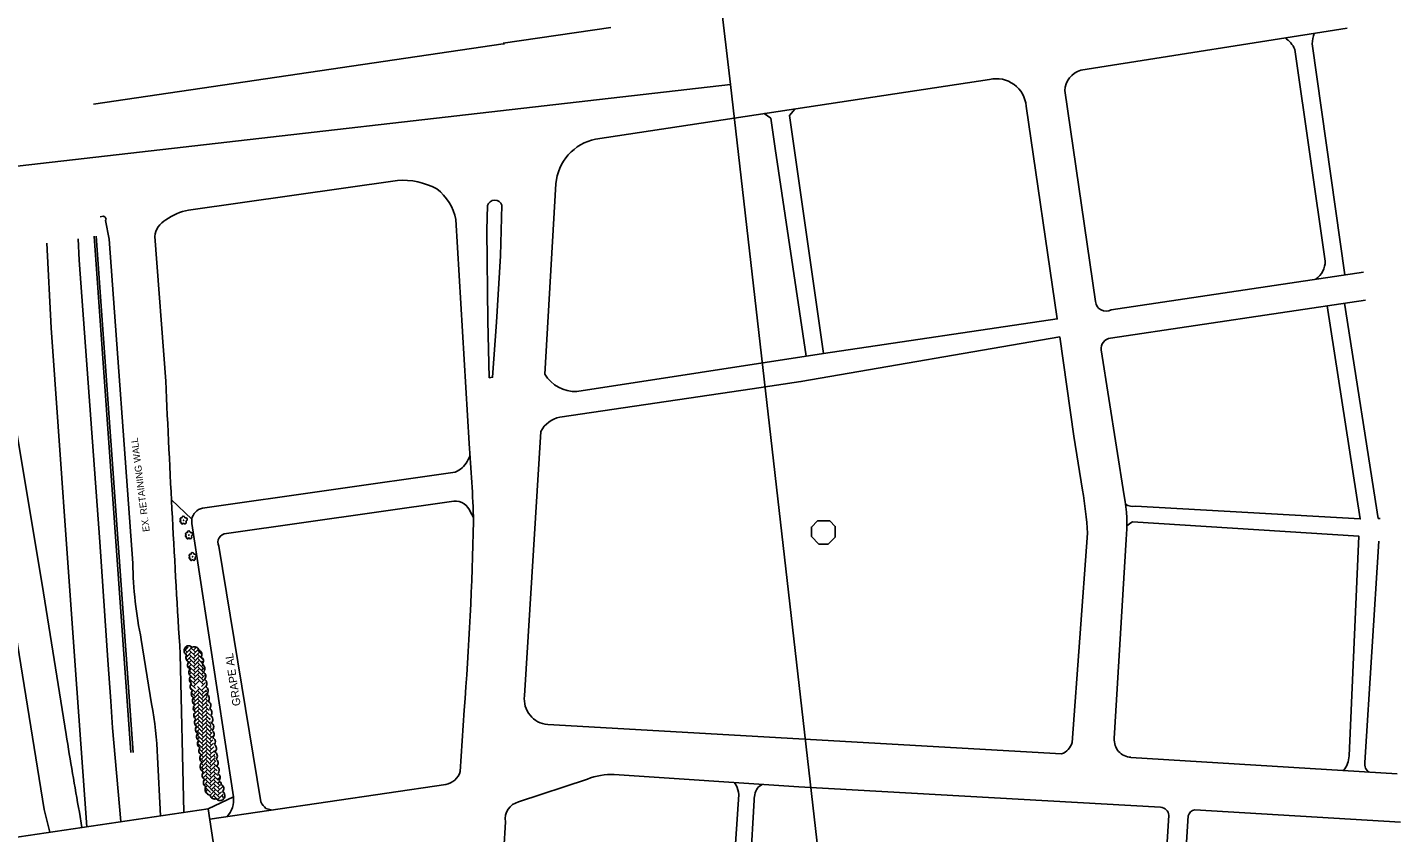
# Model space of a CAD drawing. Extents: x -9648 to 41057, y -12373 to 40276.
# Drawn here: x 9212 to 10174, y -1624 to -1060 of the extents above; entities that cross this region are included whole.
import ezdxf

# ---------------------------------------------------------------- set-up
doc = ezdxf.new("R2010")
doc.units = 0
doc.layers.add('SC_Scratch1', color=7, linetype='Continuous')
doc.layers.add('SH_Data', color=7, linetype='Continuous')

msp = doc.modelspace()

# ---------------------------------------------------------------- linework, layer by layer
at = {"layer": 'SC_Scratch1'}
for p, q in [((9447.3, 1145.16), (9704.49, -1100.16)), ((9447.3, 1145.16), (9704.49, -1100.16)), ((8174.5, -1275.41), (9704.49, -1100.16)), ((9704.49, -1100.16), (8174.5, -1275.41)), ((9704.49, -1100.16), (8174.5, -1275.41)), ((9704.49, -1100.16), (9961.68, -3345.48))]:
    msp.add_line(p, q, dxfattribs=at)
at = {"layer": 'SH_Data'}
for p, q in [((9545.55, -1071.29), (9620.74, -1060.25)), ((9949.76, -1090.26), (10136.31, -1060.72)), ((9258.78, -1113.84), (9545.55, -1071.81)), ((9545.55, -1071.81), (9546.35, -1071.69)), ((10099.55, -1075.57), (10120.83, -1223.76)), ((10111.75, -1071.77), (10134.51, -1233.49)), ((9610.18, -1138.45), (9885.96, -1096.7)), ((9960.05, -1252.05), (9938.57, -1104.47)), ((9325.21, -1188.21), (9471.4, -1167.33)), ((9574.68, -1302.87), (9582.4, -1169.67)), ((9263.42, -1192.85), (9265.42, -1192.44)), ((9512.42, -1194.71), (9521.7, -1351.5)), ((9259.16, -1206.36), (9284.93, -1567.94)), ((9260.66, -1206.26), (9286.42, -1567.83)), ((9309.28, -1307.77), (9301.62, -1206.62)), ((10147.75, -1231.51), (9971.05, -1257.85)), ((9970.66, -1277.85), (10149.07, -1251.11)), ((9980.12, -1388.24), (9964.07, -1286.05)), ((9560.4, -1528.28), (9571.9, -1343.07)), ((9520.31, -1364.1), (9522.11, -1360.5)), ((9334.93, -1396.81), (9511.91, -1371.51)), ((9313.28, -1390.92), (9327.53, -1404.59)), ((9510.93, -1391.9), (9351.74, -1414.59)), ((9524.73, -1403.3), (9522.53, -1399.7)), ((9238.65, -1405.75), (9247.03, -1522.96)), ((9356.64, -1598.79), (9327.53, -1407.41)), ((9954.54, -1414.26), (9943.82, -1560.86)), ((9973.22, -1558.05), (9981.54, -1418.84)), ((10158.34, -1419.94), (10148.63, -1574.75)), ((9346.54, -1423.4), (9375.85, -1602.38)), ((9292.18, -1488.83), (9299.4, -1533.82)), ((9322.05, -1609.61), (9319.39, -1498.98)), ((9324.35, -1497.67), (9322.85, -1496.18)), ((9322.93, -1496.26), (9325.07, -1494.11)), ((9323.21, -1498.81), (9327.18, -1494.84)), ((9324.35, -1494.84), (9323.47, -1493.97)), ((9323.55, -1501.3), (9327.18, -1497.67)), ((9330.01, -1500.5), (9325.76, -1496.26)), ((9330.01, -1503.33), (9325.76, -1499.09)), ((9330.01, -1497.67), (9326.59, -1494.25)), ((9328.59, -1496.26), (9330.25, -1494.59)), ((9328.59, -1499.08), (9332.2, -1495.47)), ((9328.59, -1501.91), (9332.83, -1497.67)), ((9330, -1494.84), (9329.7, -1494.54)), ((9334.47, -1499.3), (9331.42, -1496.26)), ((9334.9, -1502.56), (9331.42, -1499.08)), ((9334.25, -1499.08), (9334.42, -1498.91)), ((9270.73, -1531.81), (9268.78, -1503.17)), ((9324.35, -1503.33), (9323.74, -1502.72)), ((9324.35, -1500.5), (9323.79, -1499.94)), ((9324.13, -1503.55), (9327.18, -1500.5)), ((9324.65, -1505.86), (9327.18, -1503.33)), ((9325.07, -1508.27), (9327.18, -1506.16)), ((9330.01, -1506.16), (9325.76, -1501.91)), ((9330.01, -1508.98), (9325.76, -1504.74)), ((9330.01, -1511.81), (9325.77, -1507.57)), ((9328.59, -1504.74), (9332.83, -1500.49)), ((9328.6, -1507.57), (9332.84, -1503.32)), ((9328.6, -1510.4), (9332.84, -1506.15)), ((9330.81, -1499.66), (9330.81, -1499.66)), ((9335.1, -1505.58), (9331.42, -1501.91)), ((9335.67, -1508.98), (9331.42, -1504.74)), ((9335.54, -1511.68), (9331.43, -1507.57)), ((9334.25, -1501.91), (9334.67, -1501.49)), ((9334.25, -1504.74), (9335.07, -1503.91)), ((9334.25, -1507.56), (9335.41, -1506.41)), ((9325.6, -1510.57), (9327.18, -1508.98)), ((9330.01, -1514.64), (9325.77, -1510.4)), ((9325.77, -1513.23), (9327.18, -1511.81)), ((9326.94, -1514.4), (9325.77, -1513.23)), ((9330.02, -1520.29), (9325.91, -1516.19)), ((9326, -1515.82), (9327.19, -1514.64)), ((9326.3, -1518.36), (9327.19, -1517.47)), ((9330.01, -1517.47), (9326.96, -1514.42)), ((9328.6, -1513.23), (9332.84, -1508.98)), ((9328.6, -1516.06), (9332.84, -1511.81)), ((9328.6, -1518.88), (9332.84, -1514.64)), ((9328.61, -1521.71), (9332.84, -1517.47)), ((9335.67, -1514.64), (9331.43, -1510.39)), ((9335.67, -1517.46), (9331.43, -1513.22)), ((9335.67, -1520.29), (9331.43, -1516.05)), ((9334.26, -1510.39), (9335.74, -1508.91)), ((9334.26, -1513.22), (9335.68, -1511.8)), ((9334.26, -1516.05), (9336.4, -1513.91)), ((9334.26, -1518.88), (9336.42, -1516.72)), ((9335.67, -1511.81), (9335.65, -1511.78)), ((9254.05, -1619.85), (9247.03, -1522.96)), ((9330.02, -1525.95), (9326.41, -1522.35)), ((9326.42, -1521.07), (9327.19, -1520.3)), ((9326.86, -1523.46), (9327.19, -1523.13)), ((9330.02, -1523.12), (9326.88, -1519.98)), ((9330.02, -1528.78), (9327.24, -1526.01)), ((9328.61, -1527.37), (9332.85, -1523.12)), ((9328.61, -1530.2), (9332.85, -1525.95)), ((9335.68, -1525.95), (9331.43, -1521.71)), ((9335.68, -1528.78), (9331.43, -1524.54)), ((9335.68, -1531.61), (9331.44, -1527.37)), ((9334.26, -1521.71), (9337.05, -1518.91)), ((9334.26, -1524.54), (9337.38, -1521.41)), ((9334.26, -1527.36), (9337.71, -1523.91)), ((9334.26, -1530.19), (9338.04, -1526.41)), ((9337.47, -1522.09), (9337.09, -1521.71)), ((9337.9, -1525.34), (9337.09, -1524.54)), ((9338.33, -1528.6), (9337.09, -1527.36)), ((9330.03, -1534.44), (9328.01, -1532.42)), ((9330.02, -1531.61), (9328.47, -1530.06)), ((9328.61, -1533.02), (9332.85, -1528.78)), ((9330.03, -1537.27), (9328.7, -1535.94)), ((9328.8, -1535.66), (9332.85, -1531.61)), ((9328.97, -1538.33), (9332.86, -1534.44)), ((9329.13, -1541), (9332.86, -1537.26)), ((9335.68, -1534.44), (9331.44, -1530.19)), ((9335.68, -1537.26), (9331.44, -1533.02)), ((9335.69, -1540.09), (9331.44, -1535.85)), ((9334.27, -1533.02), (9338.37, -1528.91)), ((9334.27, -1535.85), (9338.51, -1531.61)), ((9334.27, -1538.68), (9338.51, -1534.43)), ((9334.27, -1541.51), (9338.51, -1537.26)), ((9338.76, -1531.85), (9337.09, -1530.19)), ((9339.19, -1535.11), (9337.09, -1533.02)), ((9339.62, -1538.37), (9337.1, -1535.85)), ((9330.03, -1542.92), (9329.08, -1541.97)), ((9329.43, -1543.53), (9332.86, -1540.09)), ((9329.64, -1546.14), (9332.86, -1542.92)), ((9330.03, -1545.75), (9329.71, -1545.43)), ((9330.03, -1540.09), (9329.79, -1539.86)), ((9329.98, -1548.63), (9332.86, -1545.75)), ((9335.69, -1542.92), (9331.44, -1538.68)), ((9335.69, -1545.75), (9331.44, -1541.51)), ((9335.69, -1548.58), (9331.44, -1544.34)), ((9335.69, -1551.41), (9331.45, -1547.16)), ((9334.27, -1544.34), (9338.51, -1540.09)), ((9334.28, -1547.16), (9338.51, -1542.92)), ((9334.28, -1549.99), (9338.52, -1545.75)), ((9340.05, -1541.62), (9337.1, -1538.68)), ((9340.47, -1544.88), (9337.1, -1541.51)), ((9340.91, -1548.13), (9337.1, -1544.33)), ((9341.34, -1551.39), (9337.1, -1547.16)), ((9339.93, -1541.51), (9340.02, -1541.41)), ((9339.93, -1544.33), (9340.35, -1543.91)), ((9339.93, -1547.16), (9340.68, -1546.41)), ((9518.21, -1538.3), (9515.43, -1581.1)), ((9330.03, -1548.58), (9329.97, -1548.51)), ((9330.32, -1551.12), (9332.86, -1548.58)), ((9330.68, -1553.59), (9332.86, -1551.41)), ((9331, -1556.11), (9332.86, -1554.24)), ((9335.69, -1554.23), (9331.45, -1549.99)), ((9335.69, -1557.06), (9331.45, -1552.82)), ((9335.7, -1559.89), (9331.45, -1555.65)), ((9334.28, -1552.82), (9338.52, -1548.58)), ((9334.28, -1555.65), (9338.52, -1551.41)), ((9334.28, -1558.48), (9338.52, -1554.23)), ((9341.35, -1554.23), (9337.11, -1549.99)), ((9341.35, -1557.06), (9337.11, -1552.82)), ((9341.35, -1559.89), (9337.11, -1555.65)), ((9339.93, -1549.99), (9341.01, -1548.91)), ((9339.94, -1552.82), (9341.34, -1551.41)), ((9339.94, -1555.64), (9341.67, -1553.91)), ((9339.94, -1558.47), (9342, -1556.41)), ((9936.23, -1568.87), (9576.61, -1548.27)), ((9331.34, -1558.6), (9332.87, -1557.06)), ((9335.7, -1562.72), (9331.45, -1558.48)), ((9331.68, -1561.09), (9332.87, -1559.89)), ((9335.7, -1565.55), (9331.74, -1561.6)), ((9332.11, -1563.48), (9332.87, -1562.72)), ((9332.54, -1565.88), (9332.87, -1565.55)), ((9335.7, -1568.38), (9332.71, -1565.39)), ((9334.28, -1561.31), (9338.52, -1557.06)), ((9334.28, -1564.13), (9338.52, -1559.89)), ((9334.29, -1566.96), (9338.53, -1562.72)), ((9334.29, -1569.79), (9338.53, -1565.54)), ((9341.36, -1562.72), (9337.11, -1558.48)), ((9341.36, -1565.54), (9337.11, -1561.31)), ((9341.36, -1568.37), (9337.11, -1564.13)), ((9339.94, -1561.3), (9342.33, -1558.91)), ((9339.94, -1564.13), (9342.66, -1561.41)), ((9339.94, -1566.96), (9342.99, -1563.91)), ((9339.94, -1569.79), (9343.31, -1566.41)), ((9343.05, -1564.41), (9342.77, -1564.13)), ((9303.43, -1571.02), (9305.65, -1612.22)), ((9335.71, -1574.03), (9333.14, -1571.48)), ((9335.7, -1571.21), (9334.07, -1569.57)), ((9335.71, -1576.86), (9334.15, -1575.3)), ((9334.29, -1572.62), (9338.53, -1568.37)), ((9334.29, -1575.45), (9338.53, -1571.2)), ((9334.29, -1578.28), (9338.53, -1574.03)), ((9341.36, -1571.2), (9337.11, -1566.96)), ((9341.36, -1574.03), (9337.12, -1569.79)), ((9341.36, -1576.86), (9337.12, -1572.62)), ((9341.36, -1579.69), (9337.12, -1575.44)), ((9339.94, -1572.62), (9343.65, -1568.91)), ((9339.95, -1575.44), (9343.97, -1571.41)), ((9339.95, -1578.27), (9344.19, -1574.03)), ((9343.48, -1567.67), (9342.77, -1566.96)), ((9343.91, -1570.92), (9342.77, -1569.79)), ((9344.34, -1574.18), (9342.77, -1572.61)), ((9344.77, -1577.43), (9342.78, -1575.44)), ((10171.3, -1582.89), (9984.83, -1571.24)), ((9335.71, -1579.69), (9333.96, -1577.95)), ((9334.63, -1580.76), (9338.53, -1576.86)), ((9334.78, -1583.45), (9338.54, -1579.69)), ((9335.71, -1585.35), (9334.85, -1584.49)), ((9335.71, -1582.52), (9335.27, -1582.08)), ((9335.37, -1585.69), (9338.54, -1582.52)), ((9335.67, -1588.22), (9338.54, -1585.34)), ((9335.71, -1581.55), (9335.71, -1581.55)), ((9335.71, -1581.55), (9335.71, -1581.55)), ((9341.37, -1582.51), (9337.12, -1578.27)), ((9341.37, -1585.34), (9337.12, -1581.1)), ((9341.37, -1588.17), (9337.12, -1583.93)), ((9339.95, -1581.1), (9344.19, -1576.86)), ((9339.95, -1583.93), (9344.19, -1579.69)), ((9339.96, -1586.76), (9344.19, -1582.51)), ((9339.96, -1589.59), (9344.19, -1585.34)), ((9345.2, -1580.69), (9342.78, -1578.27)), ((9345.63, -1583.94), (9342.78, -1581.1)), ((9346.05, -1587.2), (9342.78, -1583.93)), ((9345.61, -1583.93), (9345.62, -1583.92)), ((9345.61, -1586.76), (9346.89, -1585.48)), ((9335.71, -1588.18), (9335.69, -1588.15)), ((9336.09, -1590.62), (9338.54, -1588.17)), ((9336.88, -1592.67), (9338.54, -1591)), ((9337.09, -1595.28), (9338.54, -1593.83)), ((9341.37, -1591), (9337.13, -1586.76)), ((9342.3, -1594.76), (9337.13, -1589.59)), ((9340.55, -1595.83), (9337.13, -1592.42)), ((9339.44, -1597.55), (9337.13, -1595.24)), ((9339.96, -1592.41), (9344.2, -1588.17)), ((9505.24, -1590.31), (9340.25, -1614.6)), ((9340.26, -1597.77), (9344.2, -1593.83)), ((9340.91, -1594.29), (9344.2, -1591)), ((9341.85, -1593.42), (9341.85, -1593.42)), ((9347.03, -1591), (9342.78, -1586.76)), ((9347.03, -1593.83), (9342.78, -1589.59)), ((9347.03, -1596.65), (9342.79, -1592.41)), ((9347.03, -1599.48), (9342.79, -1595.24)), ((9345.61, -1589.58), (9347.09, -1588.1)), ((9345.61, -1592.41), (9347.6, -1590.42)), ((9345.62, -1595.24), (9349.32, -1591.54)), ((9604.43, -1586.45), (9556.24, -1602.48)), ((9708.64, -1590.8), (9707.07, -1588.91)), ((9726.68, -1590.24), (9724.24, -1591.79)), ((9338.31, -1596.9), (9338.54, -1596.66)), ((9339.05, -1607.2), (9356.64, -1598.79)), ((9341.24, -1599.62), (9344.2, -1596.66)), ((9345.91, -1601.19), (9342.79, -1598.07)), ((9343.23, -1600.46), (9344.2, -1599.48)), ((9345.62, -1598.07), (9348.28, -1595.41)), ((9345.62, -1600.9), (9349.54, -1596.97)), ((9347.83, -1601.52), (9347.93, -1601.41)), ((9349.82, -1599.44), (9348.44, -1598.07)), ((9690, -1889.81), (9710.44, -1597.2)), ((9248.85, -1609.65), (9250.46, -1620.25)), ((9379.45, -1606.98), (9383.17, -1607.9)), ((9993.22, -1909.43), (10011.45, -1611.82)), ((10024.85, -1612.22), (10017.12, -1733.42)), ((10173.56, -1616.71), (10029.65, -1608.02)), ((9547.05, -1616.28), (9545.86, -1636.08))]:
    msp.add_line(p, q, dxfattribs=at)
for points in [[(9911.57, -1115.28), (9933.26, -1264.27), (9769.67, -1288.56), (9597.08, -1315.06)], [(9728.09, -1120.6), (9732.78, -1123.78), (9735.79, -1144.98), (9757.59, -1290.42)], [(9769.67, -1288.56), (9745.98, -1121.97), (9749.57, -1117.34)], [(9535.68, -1305.44), (9534.66, -1265.58), (9534.05, -1202.14), (9534.48, -1184.99)], [(9544.63, -1184.73), (9543.64, -1220.12), (9540.78, -1266.59), (9538.09, -1305.13), (9535.68, -1305.44)], [(9267.22, -1195.44), (9269.62, -1208.44), (9286.15, -1435.23)], [(9268.78, -1503.17), (9263.14, -1420.44), (9248.63, -1223.25), (9248.02, -1208.25)], [(9228.05, -1623.67), (9224.27, -1607.77), (9205.62, -1491.89), (9187.33, -1375.77), (9162.03, -1220.5)], [(9184.03, -1217.29), (9205.31, -1345.51), (9222.77, -1450.31), (9239.62, -1555.23)], [(9238.65, -1405.75), (9236.53, -1375.75), (9229.05, -1270.49), (9226.02, -1211.27)], [(9988.13, -1395.44), (10145.33, -1404.35), (10122.24, -1255.12)], [(10134.25, -1253.33), (10157.93, -1403.94), (10159.32, -1404.04)], [(9585.09, -1333.07), (9719.68, -1313.19), (9753.88, -1308.17), (9935.06, -1276.87)], [(9935.06, -1276.87), (9944.9, -1346.46), (9950.92, -1384.26)], [(9985.93, -1406.44), (10144.34, -1416.35), (10137.63, -1570.15)], [(9277.85, -1616.24), (9272.02, -1550.64), (9270.73, -1531.81)], [(9335.71, -1581.55), (9335.71, -1581.55)], [(10005.65, -1606.23), (9752.44, -1591.97), (9623.23, -1583.24)], [(9721.25, -1601.19), (9713.52, -1734.19), (10002.89, -1751.5)]]:
    msp.add_lwpolyline(points, dxfattribs=at)
for points in [[(9761.18, -1416.74), (9761.18, -1410.01), (9765.47, -1405.71), (9774.04, -1405.71), (9777.89, -1409.6), (9777.89, -1417), (9772.86, -1422.03), (9766.43, -1422.03)], [(9124.46, -1638.92), (9339.05, -1607.2), (9345.87, -1653.6), (9131.29, -1685.32)]]:
    msp.add_lwpolyline(points, close=True, dxfattribs=at)
for centre in [(9321.72, -1405.3), (9325.5, -1415.65), (9328.04, -1430.77)]:
    msp.add_circle(centre, 0.151, dxfattribs=at)
for centre, radius, start, end in [((10145.21, -1074.23), 33.56, 162.94118, 175.79118), ((10083.85, -1082.13), 17.01, 22.67918, 58.56618), ((9953.93, -1105.05), 15.37, 105.73518, 177.80118), ((9890.73, -1117.06), 20.91, 4.87218, 103.19018), ((9616.93, -1172.42), 34.63, 101.22518, 175.43618), ((9475.05, -1217.13), 49.93, 61.33918, 94.19618), ((9477.34, -1201.8), 35.79, 11.42818, 52.74318), ((9539.6, -1186.48), 5.33, 19.16818, 163.83318), ((9331.26, -1223.97), 36.27, 99.60118, 127.03518), ((9265.47, -1194.45), 2.01, 330.36518, 91.62618), ((9316.38, -1208.11), 14.83, 117.99218, 174.23718), ((10105.62, -1223.99), 15.21, 304.73918, 0.86918), ((9967.36, -1251.52), 7.33, 184.19218, 300.26918), ((9971.26, -1285.08), 7.26, 94.70818, 187.69618), ((9595.79, -1290.74), 24.35, 209.87718, 273.03818), ((20693.09, -801.91), 11395.04, 182.544183, 183.507183), ((9588.83, -1351.7), 19.01, 101.35418, 153.00418), ((8319.11, -1445.64), 1206.27, 1.87818, 4.47618), ((9505.26, -1355.49), 17.34, 292.57718, 330.24418), ((9512.03, -1402.8), 10.95, 16.44218, 95.78718), ((9671.13, -1433.21), 284.04, 3.82618, 9.92418), ((9874.9, -1408.45), 107.14, 354.43318, 10.87018), ((9321.61, -1403.44), 1.03, 351.9296, 194.2439), ((9336.8, -1405.99), 9.37, 101.50918, 171.43061), ((9986.48, -1385.23), 10.34, 238.14218, 279.15218), ((9319.94, -1405.92), 0.71, 86.78898, 298.7584), ((9320.15, -1404.39), 0.837, 56.61424, 257.82189), ((9320.81, -1407.13), 0.793, 131.84683, 12.32553), ((9322.63, -1406.8), 1.06, 188.95648, 53.358), ((9323.1, -1404.72), 1.23, 277.73186, 112.24144), ((9325.39, -1413.79), 1.03, 351.9296, 194.2439), ((9339.53, -1405.99), 12.08, 173.37778, 186.77007), ((7121.28, -1353.72), 2404.02, 355.59618, 358.75118), ((9995.43, -1424.27), 20.2, 118.03518, 131.72118), ((9323.71, -1416.27), 0.71, 86.78898, 298.7584), ((9323.93, -1414.74), 0.837, 56.61424, 257.82189), ((9324.58, -1417.48), 0.793, 131.84683, 12.32553), ((9326.41, -1417.15), 1.06, 188.95648, 53.358), ((9326.88, -1415.08), 1.23, 277.73186, 112.24144), ((9351.69, -1420.5), 5.9, 89.48118, 209.42518), ((9326.25, -1431.39), 0.71, 86.78898, 298.7584), ((9326.47, -1429.86), 0.837, 56.61424, 257.82189), ((9327.93, -1428.91), 1.03, 351.9296, 194.2439), ((9328.94, -1432.27), 1.06, 188.95648, 53.358), ((9329.41, -1430.19), 1.23, 277.73186, 112.24144), ((9587.66, -1428.45), 301.59, 181.28918, 191.54918), ((9327.12, -1432.6), 0.793, 131.84683, 12.32553), ((9325.19, -1496.55), 3.13, 139.75605, 249.75605), ((9325.39, -1496.16), 3.06, 37.78429, 147.78429), ((9329.47, -1496.87), 3.07, 12.75912, 122.75912), ((9331.51, -1499.1), 3.06, 321.81545, 71.81545), ((9326.5, -1501.51), 3.13, 139.75599, 249.75599), ((9327.66, -1506.58), 3.1, 136.39672, 246.39672), ((9332.6, -1503.78), 3.08, 314.69288, 64.69288), ((9333.13, -1509.1), 3.54, 312.29659, 62.29659), ((9328.44, -1511.72), 3.07, 131.25118, 241.25118), ((9328.92, -1516.77), 3.06, 129.51938, 239.51938), ((9334.19, -1514.5), 3.08, 314.69293, 64.69293), ((9335.04, -1519.48), 3.08, 314.69293, 64.69293), ((9329.51, -1521.74), 3.17, 132.8248, 242.8248), ((9330.24, -1526.74), 3.08, 134.69293, 244.69293), ((9335.66, -1524.65), 3.35, 312.5461, 62.5461), ((9336.69, -1529.95), 3.1, 316.39672, 66.39672), ((9082.63, -1576.07), 220.85, 1.31018, 11.02818), ((9331.01, -1531.78), 3.07, 132.97672, 242.97672), ((9331.64, -1536.83), 3.07, 131.25124, 241.25124), ((9337.69, -1534.93), 3.1, 316.39672, 66.39672), ((9338.54, -1539.8), 3.07, 312.97678, 62.97678), ((9578.11, -1530.49), 17.85, 172.89318, 265.18618), ((9332.04, -1541.93), 3.06, 127.78429, 237.78429), ((9332.43, -1546.83), 3.07, 131.25118, 241.25118), ((9339.16, -1544.74), 3.07, 311.25118, 61.25118), ((9339.6, -1549.89), 3.25, 311.05352, 61.05352), ((11156.04, -1258.19), 1939.31, 188.81018, 190.44118), ((9333.12, -1551.71), 3.08, 134.69293, 244.69293), ((9333.83, -1556.8), 3.07, 131.25118, 241.25118), ((9340.11, -1554.93), 3.06, 307.78429, 57.78429), ((9334.6, -1561.63), 3.1, 136.39672, 246.39672), ((9335.52, -1566.66), 3.08, 134.69293, 244.69293), ((9340.9, -1560.29), 3.13, 319.75605, 69.75605), ((9341.61, -1564.98), 3.15, 307.78429, 57.78429), ((9931.81, -1557.07), 12.59, 290.51218, 342.49018), ((9985.49, -1558.95), 12.3, 175.76518, 266.91618), ((9336.29, -1571.83), 3.16, 131.14945, 241.14945), ((9337.67, -1577.74), 4.28, 132.75216, 242.75216), ((9342.3, -1570.31), 3.1, 316.39672, 66.39672), ((9342.91, -1575.03), 3.06, 307.78429, 57.78429), ((10118.86, -1569.02), 18.8, 322.18018, 356.53918), ((10154.92, -1576.09), 6.43, 167.95318, 240.09118), ((9337.93, -1583.81), 3.18, 134.49162, 244.49162), ((9343.42, -1580.32), 3.18, 314.49156, 64.49156), ((9344.25, -1585.32), 3.07, 312.97678, 62.97678), ((9502.71, -1577.26), 13.29, 280.97118, 343.19118), ((9621.3, -1628.55), 45.35, 87.55418, 111.82918), ((9338.66, -1588.93), 3.07, 132.97672, 242.97672), ((9340.93, -1593.65), 4.17, 151.54919, 261.54919), ((9339.36, -1593.91), 3.07, 132.97678275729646, 132.97678441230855), ((9344.8, -1590.55), 3.35, 5.12803, 62.5461), ((9346.77, -1593.06), 3.13, 314.21479, 64.21479), ((9347.6, -1598.12), 3.13, 314.21484, 64.21484), ((9691.27, -1599.14), 19.27, 5.80718, 25.67418), ((9734.6, -1600.26), 13.39, 140.71018, 183.95318), ((9343.37, -1597.4), 3.07, 187.21792, 297.21792), ((9347.36, -1598.49), 3.06, 212.24308, 322.24308), ((9339.28, -1600.9), 17.49, 316.85821, 6.936), ((9387.29, -1597.13), 12.59, 204.66918, 231.48918), ((9559.01, -1614.28), 12.12, 103.17018, 189.51418), ((10005.24, -1612.45), 6.24, 5.78118, 86.29318), ((10030.61, -1613.95), 6.02, 99.21218, 163.22418)]:
    msp.add_arc(centre, radius, start, end, dxfattribs=at)

# ---------------------------------------------------------------- texts
at = {"layer": 'SC_Scratch1'}
for s, height, rotation, p in [('EX. RETAINING WALL', 4.8, 97.3206, (9298.08, -1413)), ('GRAPE AL', 5.6, 98.34324, (9361.73, -1534.89))]:
    msp.add_text(s, height=height, rotation=rotation, dxfattribs=at).set_placement(p)

doc.saveas('drawing.dxf')
